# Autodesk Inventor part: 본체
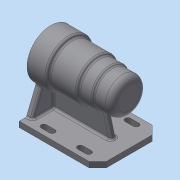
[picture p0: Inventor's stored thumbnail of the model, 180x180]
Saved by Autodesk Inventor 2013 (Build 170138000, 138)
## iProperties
Created: 2017-09
Part Number: 본체
Material: Generic
Document SubType Name: Modeling
Designer: Administrator
Density: 1 g/cm^3
Author: Administrator
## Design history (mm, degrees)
sketch "스케치2"
  geometry: L1 (0, 0)-(-112, 0); L2 (0, 0)-(0, 34); L3 (0, 34)-(-28, 34); L4 (-28, 34)-(-28, 30); L5 (-28, 30)-(-67, 30); L6 (-67, 30)-(-67, 27); L7 (-67, 27)-(-87, 27); L8 (-87, 27)-(-87, 25); L9 (-87, 25)-(-112, 25); L10 (-112, 25)-(-112, 0); L11 (0, 21)-(-15, 21); L12 (-15, 21)-(-15, 21); L13 (-18, 24)-(-66, 24); L14 (-69, 21)-(-69, 21); L15 (-69, 21)-(-80.7, 21); L16 (-81, 20.7)-(-81, 17.5); L17 (-81, 17.5)-(-98.7, 17.5); L18 (-99, 17.2)-(-99, 16); L19 (-99, 16)-(-102.7, 16); L20 (-103, 10.5)-(-103, 10.5); L21 (-106, 7.5)-(-106, 0); L22 (-103, 10.5)-(-103, 15.7); A1 r 0.3 centre (-102.7, 15.7) between (-102.7, 16) and (-103, 15.7); A2 r 0.3 centre (-98.7, 17.2) between (-98.7, 17.5) and (-99, 17.2); A3 r 0.3 centre (-80.7, 20.7) between (-80.7, 21) and (-81, 20.7); A4 r 3 centre (-18, 21) between (-15, 21) and (-18, 24); A5 r 3 centre (-66, 21) between (-66, 24) and (-69, 21); A6 r 3 centre (-103, 7.5) between (-103, 10.5) and (-106, 7.5); 6 further points
  constraints: 44 end point, 14 point on line, 12 parallel, 12 point on circle, 12 tangent, 8 perpendicular, 6 centre point, 4 equal radius, 1 collinear, 1 horizontal
  dimensions: "d1" = 68 diameter of L3 L1; "d3" = 60 diameter of L5 L1; "d4" = 54 diameter of L7 L1; "d5" = 50 diameter of L9 L1; "d6" = 25 distance of L8.end L9.end; "d7" = 112 distance of L1.start L1.end; "d8" = 45 distance between parallel lines of L10 L6; "d9" = 84 distance between parallel lines of L10 L4; "d10" = 15 distance of L11.start L11.end; "d11" = 54 distance of point (-15, 24) point (-69, 24); "d12" = 12 distance of L14.end point (-81, 21); "d13" = 18 distance of L16.end point (-99, 17.5); "d14" = 4 distance of L18.end point (-103, 16); "d15" = 3 distance of L20.start point (-106, 10.5); "d16" = 42 diameter of L11 L1; "d17" = 48 diameter of L13 L1; "d18" = 42 diameter of L15 L1; "d19" = 35 diameter of L17 L1; "d20" = 32 diameter of L19 L1; "d21" = 21 diameter of L20 L1; "d22" = 0.3 radius of A1; "d23" = 3 radius of A4
revolve "회전1" sketch "스케치2" stored, may be unused: angle "d24" = 90 deg
node "작업 평면1"
sketch "스케치3"
  geometry: L1 (0, 45)-(112, 45); L2 (112, 45)-(112, -45); L3 (112, -45)-(0, -45); L4 (0, -45)-(0, 45); 2 further points
  constraints: 8 end point, 2 parallel, 1 coincident, 1 horizontal, 1 midpoint, 1 perpendicular
  dimensions: "d26" = 90 distance of L3.end L1.start; "d28" = 112 distance of L1.start L1.end
extrude "돌출1" join sketch "스케치3" distance "d29" = 8; taper "d30" = 0 deg
sketch "스케치4"
  geometry: L1 (-70, -45)-(-70, 45) reference; L2 (-70, -45)-(-62, -45) reference; L3 (-62, 45)-(-62, -45) reference; L4 (-70, 45)-(-62, 45) reference; L5 (-26.885, -20.813)-(-62, -35); L6 (-26.885, 20.813)-(-62, 35); A1 r 34 centre (0, 0) between (-26.885, -20.813) and (-26.885, 20.813) reference
  constraints: 4 end point, 2 point on circle, 2 point on line
  dimensions: "d31" = 10 distance from line of L6.end L4; "d32" = 10 distance from line of L2 L5.end; "d33" = 112 deg angle of L3 L5; "d34" = 112 deg angle of L3 L6
extrude "돌출2" join sketch "스케치4" distance "d35" = 8; taper "d36" = 0 deg
sketch "스케치5"
  geometry: L1 (-87, -27)-(-67, -27) reference; L2 (0, -62)-(-112, -62) reference; L3 (-112, -25)-(-87, -25) reference; L4 (-90, -62)-(-80.622, -27); L5 (-112, -70)-(-112, -62) reference; 1 further point
  constraints: 2 end point, 2 point on line
  dimensions: "d37" = 22 distance from line of L5 L4.start; "d38" = 105 deg angle of L4 L2
feature "리브1" sketch "스케치5" dims "d39" = 1, "d40" = 8, "d41" = 0, "d42" = 0, "d43" = 1, "d44" = 1
chamfer "모따기1" distance "d45" = 12; stored, may be unused: second distance "d46" = 2, angle "d47" = 45 deg
sketch "스케치6"
  geometry: L1 (112, -33)-(112, 33) reference; L2 (76, 38)-(88, 38); L3 (76, 30)-(88, 30); L4 (24, 38)-(36, 38); L5 (36, 30)-(24, 30); A1 r 4 centre (88, 34) between (88, 38) and (88, 30); A2 r 4 centre (76, 34) between (76, 38) and (76, 30); A3 r 4 centre (36, 34) between (36, 38) and (36, 30); A4 r 4 centre (24, 34) between (24, 38) and (24, 30); 1 further point
  constraints: 8 end point, 8 point on circle, 7 tangent, 4 centre point, 3 horizontal alignment, 1 parallel
  dimensions: "d48" = 34 vertical distance of A2.centre point (0, 0); "d49" = 8 diameter of A1; "d50" = 8 diameter of A2; "d51" = 12 distance of A1.centre A2.centre; "d52" = 24 distance from line of L1 A1.centre; "d53" = 8 diameter of A4; "d54" = 8 diameter of A3; "d55" = 40 distance of A2.centre A3.centre; "d56" = 12 distance of A4.centre A3.centre
extrude "돌출3" cut sketch "스케치6" distance "d57" = 8; taper "d58" = 0 deg
fillet "모깎기1" dims "d62" = 3
fillet "모깎기2" dims "d63" = 3
fillet "모깎기3" dims "d64" = 3
fillet "모깎기4" dims "d65" = 3
chamfer "모따기2" distance "d66" = 1; stored, may be unused: second distance "d67" = 2, angle "d68" = 45 deg
node "작업 평면2"
sketch "스케치7"
  geometry: L1 (-19.971, 2.402)-(18.971, 2.402); L2 (18.971, 2.402)-(18.971, -2.402); L3 (18.971, -2.402)-(-19.971, -2.402); L4 (-19.971, -2.402)-(-19.971, 2.402); L5 (-19.971, 0)-(18.971, 0); L6 (-0.5, -2.402)-(-0.5, 2.402); L7 (47.5, -22)-(47.5, 22) reference; 2 further points
  constraints: 5 midpoint, 4 end point, 1 horizontal alignment, 2 other
  dimensions: "d69" = 48 distance between parallel lines of L7 L6
feature "엠보싱1" sketch "스케치7" dims "d19" = 35, "d70" = 0.5, "d71" = 0
fillet "모깎기5" dims "d72" = 9
sketch "스케치8" dims "d73" = 52
  geometry: C1 r 22 at (70, 45) reference; C2 r 2.516 at (96, 45); A1 r 34 centre (70, 45) between (44.455, 22.562) and (44.455, 67.438) reference; 1 further point
  constraints: 2 horizontal alignment, 1 centre point, 1 coincident, 2 other
hole "구멍1" sketch "스케치8" at (96, 45) diameter "d75" = 3.242; stored, may be unused: countersink angle "d79" = 90 deg, drill point angle "d81" = 118 deg; dims "d76" = 8, "d77" = 4, "d78" = 2, "d80" = 11
node "솔리드1"
pattern_linear "직사각형 패턴1" dims "d61" = 68
pattern_circular "원형 패턴1" dims angle "d83" = 360 deg
node "투영된 루프1"
